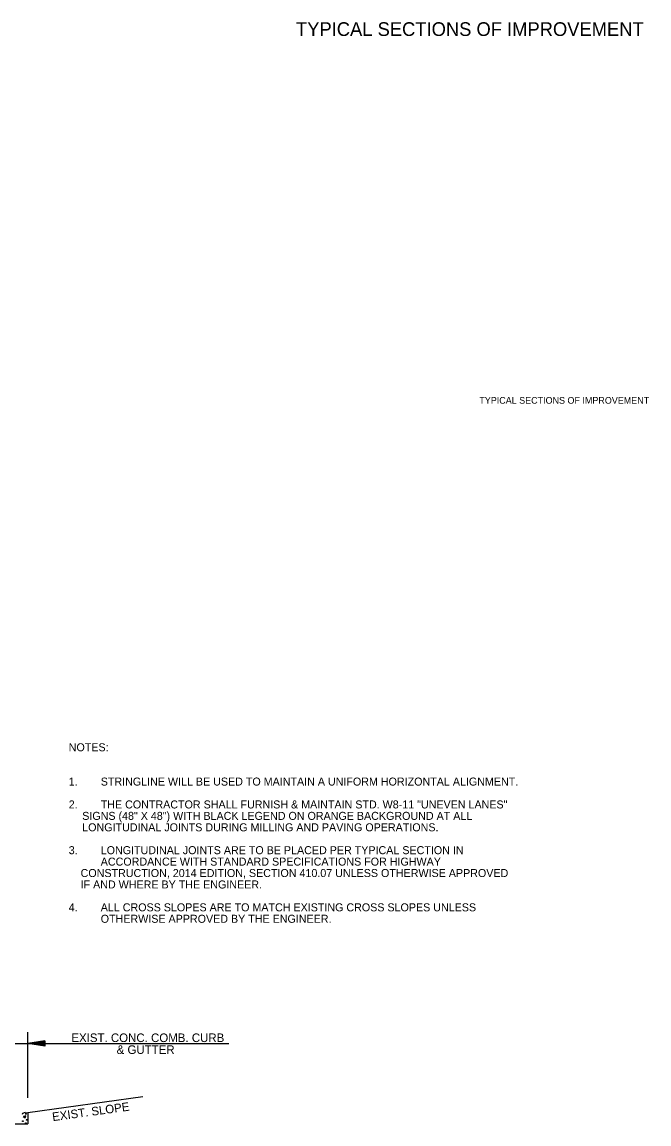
# Model space of a CAD drawing. Extents: x 542112 to 1930787, y -1968972 to 596640.
# Drawn here: x 545207 to 545755, y -1955792 to -1954829 of the extents above; entities that cross this region are included whole.
import ezdxf

# ---------------------------------------------------------------- set-up
doc = ezdxf.new("R2010")
doc.units = 0
for name, color, linetype in [('R_Border', 7, 'Continuous'), ('R_Border Notes', 7, 'Continuous'), ('R_Border Prem', 7, 'Continuous'), ('R_Draft', 7, 'Continuous')]:
    doc.layers.add(name, color=color, linetype=linetype)

msp = doc.modelspace()

# ---------------------------------------------------------------- linework, layer by layer
at = {"layer": 'R_Draft'}
for p, q in [((545211.9, -1955769.4), (545211.9, -1955712.09)), ((545196.91, -1955721.99), (545387.72, -1955721.99)), ((545226.92, -1955719.74), (545211.92, -1955721.99)), ((545226.92, -1955724.24), (545211.92, -1955721.99)), ((545226.92, -1955720.11), (545214.43, -1955721.99)), ((545226.92, -1955723.86), (545214.43, -1955721.99)), ((545226.92, -1955720.49), (545217.01, -1955721.99)), ((545226.92, -1955723.48), (545217.01, -1955721.99)), ((545226.92, -1955720.87), (545219.5, -1955721.99)), ((545226.92, -1955723.1), (545219.5, -1955721.99)), ((545226.92, -1955721.26), (545222.05, -1955721.99)), ((545226.92, -1955722.72), (545222.05, -1955721.99)), ((545226.92, -1955721.63), (545224.55, -1955721.99)), ((545226.92, -1955722.34), (545224.55, -1955721.99)), ((545226.92, -1955719.74), (545226.92, -1955724.24)), ((545312.42, -1955768.67), (545211.91, -1955782.49)), ((545209.75, -1955782.45), (545211.91, -1955782.49)), ((545211.91, -1955782.49), (545211.91, -1955792.34)), ((545196.91, -1955792.34), (545211.91, -1955792.34))]:
    msp.add_line(p, q, dxfattribs=at)
msp.add_lwpolyline([(545207.97, -1955785.91), (545209.73, -1955787.05), (545210.11, -1955785.27), (545208.21, -1955785.91)], dxfattribs=at)
for centre in [(545207.7, -1955789.92), (545210.36, -1955783.63), (545210.98, -1955788.65), (545210.16, -1955791.63)]:
    msp.add_circle(centre, 0.339, dxfattribs=at)
msp.add_arc((545209.69, -1955785.71), 3.26, 88.88036, 147.72436, dxfattribs=at)

# ---------------------------------------------------------------- texts
at = {"layer": 'R_Border'}
msp.add_text('TYPICAL SECTIONS OF IMPROVEMENT', height=12, rotation=360, dxfattribs=at).set_placement((545446.5, -1954840.7))
at = {"layer": 'R_Border Notes'}
for s, p in [('NOTES: ', (545247.75, -1955466.37)), ('1.', (545247.75, -1955496.37)), ('STRINGLINE WILL BE USED TO MAINTAIN A UNIFORM HORIZONTAL ALIGNMENT.', (545275.75, -1955496.37)), ('2.', (545247.75, -1955516.37)), ('THE CONTRACTOR SHALL FURNISH & MAINTAIN STD. W8-11 "UNEVEN LANES" ', (545275.75, -1955516.37)), ('    SIGNS (48" X 48") WITH BLACK LEGEND ON ORANGE BACKGROUND AT ALL ', (545249.15, -1955526.37)), ('    LONGITUDINAL JOINTS DURING MILLING AND PAVING OPERATIONS.', (545249.15, -1955536.37)), ('3.', (545247.75, -1955556.37)), ('LONGITUDINAL JOINTS ARE TO BE PLACED PER TYPICAL SECTION IN ', (545275.75, -1955556.37)), ('ACCORDANCE WITH STANDARD SPECIFICATIONS FOR HIGHWAY', (545275.75, -1955566.37)), ('    CONSTRUCTION, 2014 EDITION, SECTION 410.07 UNLESS OTHERWISE APPROVED', (545247.75, -1955576.37)), ('    IF AND WHERE BY THE ENGINEER.', (545247.75, -1955586.37)), ('4.', (545247.75, -1955606.37)), ('ALL CROSS SLOPES ARE TO MATCH EXISTING CROSS SLOPES UNLESS ', (545275.75, -1955606.37)), ('OTHERWISE APPROVED BY THE ENGINEER.', (545275.75, -1955616.37))]:
    msp.add_text(s, height=7, dxfattribs=at).set_placement(p)
at = {"layer": 'R_Border Prem'}
msp.add_text('TYPICAL SECTIONS OF IMPROVEMENT', height=5.862, rotation=360, dxfattribs=at).set_placement((545606.81, -1955162.38))
at = {"layer": 'R_Draft'}
for s, p in [('EXIST. CONC. COMB. CURB', (545250.07, -1955720.7)), ('& GUTTER ', (545289.66, -1955731.1))]:
    msp.add_text(s, height=7.5, dxfattribs=at).set_placement(p)
msp.add_text('EXIST. SLOPE', height=7.5, rotation=7.83179, dxfattribs=at).set_placement((545233.84, -1955789.91))

doc.saveas('drawing.dxf')
